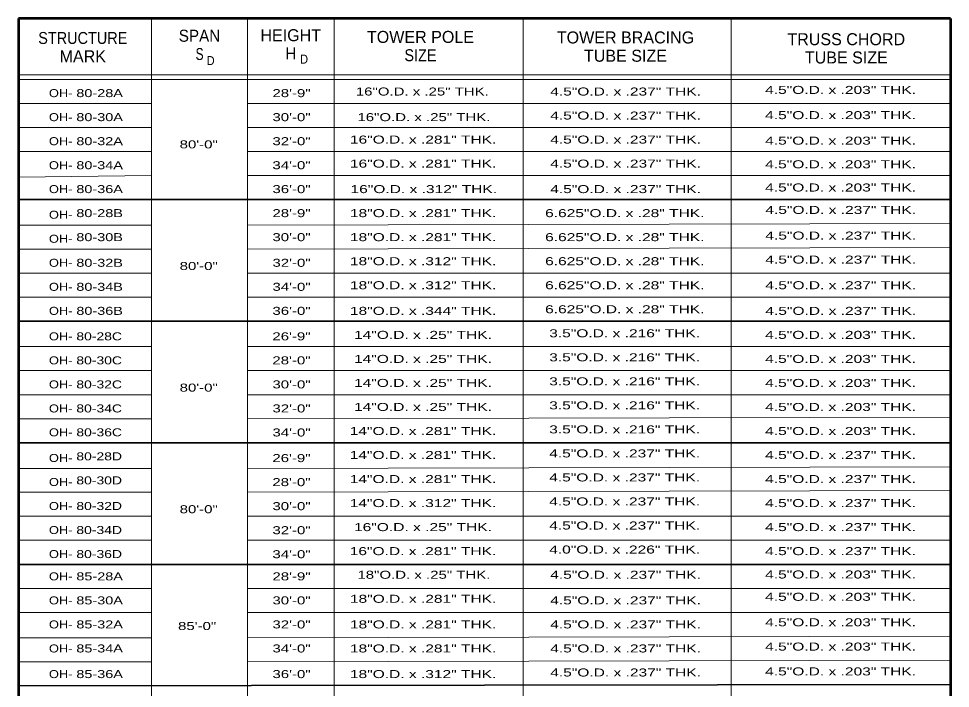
# Model space of a CAD drawing. Extents: x -34832.9 to -34825.9, y -181503 to -181493.
# Drawn here: x -34832.9 to -34825.93, y -181498.01 to -181492.99 of the extents above; entities that cross this region are included whole.
import ezdxf
from ezdxf.enums import TextEntityAlignment as Align

# ---------------------------------------------------------------- set-up
doc = ezdxf.new("R2010")
doc.units = 0
doc.header["$LTSCALE"] = 0.024
doc.layers.add('1', color=7, linetype='Continuous', lineweight=13)
doc.layers.add('13', color=7, linetype='Continuous')

msp = doc.modelspace()

# ---------------------------------------------------------------- linework, layer by layer
at = {"layer": '1', "lineweight": 53}
for p, q in [((-34825.926, -181492.988), (-34832.903, -181492.988)), ((-34832.903, -181492.988), (-34832.903, -181500.697)), ((-34825.926, -181492.988), (-34825.926, -181500.685))]:
    msp.add_line(p, q, dxfattribs=at)
at = {"layer": '1'}
for p, q in [((-34831.908, -181492.988), (-34831.908, -181500.697)), ((-34831.189, -181492.988), (-34831.189, -181500.697)), ((-34830.541, -181492.988), (-34830.541, -181500.697)), ((-34829.126, -181492.988), (-34829.126, -181500.697)), ((-34827.568, -181492.988), (-34827.568, -181500.697)), ((-34825.926, -181493.408), (-34832.903, -181493.408)), ((-34825.926, -181493.444), (-34832.903, -181493.444)), ((-34831.908, -181493.623), (-34832.903, -181493.623)), ((-34825.926, -181493.623), (-34831.189, -181493.623)), ((-34831.908, -181493.803), (-34832.903, -181493.803)), ((-34825.926, -181493.803), (-34831.189, -181493.803)), ((-34831.908, -181493.983), (-34832.903, -181493.983)), ((-34825.926, -181493.983), (-34831.189, -181493.983)), ((-34831.908, -181494.163), (-34832.903, -181494.175)), ((-34825.926, -181494.163), (-34831.189, -181494.163)), ((-34831.908, -181494.535), (-34832.903, -181494.535)), ((-34825.926, -181494.523), (-34831.189, -181494.535)), ((-34831.908, -181494.714), (-34832.903, -181494.714)), ((-34825.926, -181494.702), (-34831.189, -181494.714)), ((-34831.908, -181494.894), (-34832.903, -181494.894)), ((-34825.926, -181494.894), (-34831.189, -181494.894)), ((-34831.908, -181495.074), (-34832.903, -181495.074)), ((-34825.926, -181495.074), (-34831.189, -181495.074)), ((-34831.908, -181495.445), (-34832.903, -181495.445)), ((-34825.926, -181495.445), (-34831.189, -181495.445)), ((-34831.908, -181495.625), (-34832.903, -181495.625)), ((-34825.926, -181495.625), (-34831.189, -181495.625)), ((-34831.908, -181495.805), (-34832.903, -181495.805)), ((-34825.926, -181495.805), (-34831.189, -181495.805)), ((-34825.926, -181495.973), (-34831.189, -181495.985)), ((-34831.908, -181495.985), (-34832.903, -181495.985)), ((-34831.908, -181496.357), (-34832.903, -181496.357)), ((-34825.926, -181496.345), (-34831.189, -181496.357)), ((-34831.908, -181496.536), (-34832.903, -181496.536)), ((-34825.926, -181496.524), (-34831.189, -181496.536)), ((-34831.908, -181496.716), (-34832.903, -181496.716)), ((-34825.926, -181496.716), (-34831.189, -181496.716)), ((-34831.908, -181496.896), (-34832.903, -181496.896)), ((-34825.926, -181496.896), (-34831.189, -181496.896)), ((-34831.908, -181497.256), (-34832.903, -181497.256)), ((-34825.926, -181497.256), (-34831.189, -181497.256)), ((-34831.908, -181497.436), (-34832.903, -181497.436)), ((-34825.926, -181497.436), (-34831.189, -181497.436)), ((-34831.908, -181497.627), (-34832.903, -181497.627)), ((-34825.926, -181497.615), (-34831.189, -181497.627)), ((-34831.908, -181497.807), (-34832.903, -181497.807)), ((-34825.926, -181497.795), (-34831.189, -181497.807))]:
    msp.add_line(p, q, dxfattribs=at)
at = {"layer": '1', "lineweight": 35}
for p, q in [((-34825.926, -181494.343), (-34832.903, -181494.343)), ((-34825.926, -181495.254), (-34832.903, -181495.254)), ((-34825.926, -181496.165), (-34832.903, -181496.165)), ((-34825.926, -181497.076), (-34832.903, -181497.076)), ((-34825.926, -181497.975), (-34832.903, -181497.987))]:
    msp.add_line(p, q, dxfattribs=at)

# ---------------------------------------------------------------- texts
at = {"layer": '13'}
for s, height, width, p in [('STRUCTURE', 0.08991, 0.9, (-34832.4225, -181493.178)), ('SPAN', 0.08991, 0.95, (-34831.5485, -181493.161)), ('S', 0.0899, 0.75, (-34831.548, -181493.298)), ('H', 0.0899, 0.95, (-34830.8645, -181493.294)), ('D', 0.0674, 0.9, (-34830.765, -181493.325)), ('SIZE', 0.08991, 0.9, (-34829.894, -181493.307)), ('D', 0.0674, 0.9, (-34831.465, -181493.336)), ('OH-', 0.05992, 1.2, (-34832.588, -181493.576)), ('28\'-9"', 0.05992, 1.4, (-34830.8595, -181493.576)), ('16"O.D. x .25" THK.', 0.05992, 1.4, (-34829.88, -181493.564)), ('4.5"O.D. x .237" THK.', 0.05992, 1.45, (-34828.358, -181493.564)), ('4.5"O.D. x .203" THK.', 0.06, 1.45, (-34826.748, -181493.552)), ('OH-', 0.05992, 1.2, (-34832.588, -181493.756)), ('30\'-0"', 0.05992, 1.4, (-34830.8595, -181493.756)), ('16"O.D. x .25" THK.', 0.05992, 1.4, (-34829.868, -181493.756)), ('4.5"O.D. x .237" THK.', 0.05992, 1.45, (-34828.358, -181493.744)), ('4.5"O.D. x .203" THK.', 0.06, 1.45, (-34826.748, -181493.741)), ('OH-', 0.05992, 1.2, (-34832.588, -181493.936)), ('32\'-0"', 0.05992, 1.4, (-34830.8595, -181493.936)), ('16"O.D. x .281" THK.', 0.05992, 1.45, (-34829.874, -181493.924)), ('4.5"O.D. x .237" THK.', 0.05992, 1.45, (-34828.358, -181493.924)), ('4.5"O.D. x .203" THK.', 0.06, 1.45, (-34826.748, -181493.932)), ('80\'-0"', 0.05992, 1.4, (-34831.5545, -181493.96)), ('OH-', 0.05992, 1.2, (-34832.588, -181494.116)), ('34\'-0"', 0.05992, 1.4, (-34830.8595, -181494.116)), ('16"O.D. x .281" THK.', 0.05992, 1.45, (-34829.874, -181494.104)), ('4.5"O.D. x .237" THK.', 0.05992, 1.45, (-34828.358, -181494.104)), ('4.5"O.D. x .203" THK.', 0.06, 1.45, (-34826.748, -181494.109)), ('OH-', 0.05992, 1.2, (-34832.588, -181494.295)), ('36\'-0"', 0.05992, 1.4, (-34830.8595, -181494.295)), ('16"O.D. x .312" THK.', 0.06, 1.45, (-34829.869, -181494.295)), ('4.5"O.D. x .237" THK.', 0.05992, 1.45, (-34828.358, -181494.295)), ('4.5"O.D. x .203" THK.', 0.06, 1.45, (-34826.748, -181494.283)), ('OH-', 0.05992, 1.2, (-34832.588, -181494.487)), ('28\'-9"', 0.05992, 1.4, (-34830.8595, -181494.475)), ('18"O.D. x .281" THK.', 0.05992, 1.45, (-34829.874, -181494.475)), ('6.625"O.D. x .28" THK.', 0.05992, 1.45, (-34828.364, -181494.475)), ('4.5"O.D. x .237" THK.', 0.05992, 1.45, (-34826.747, -181494.451)), ('4.5"O.D. x .237" THK.', 0.05992, 1.45, (-34826.747, -181494.643)), ('OH-', 0.05992, 1.2, (-34832.588, -181494.667)), ('30\'-0"', 0.05992, 1.4, (-34830.8595, -181494.655)), ('18"O.D. x .281" THK.', 0.05992, 1.45, (-34829.874, -181494.655)), ('6.625"O.D. x .28" THK.', 0.05992, 1.45, (-34828.364, -181494.655)), ('OH-', 0.05992, 1.2, (-34832.588, -181494.847)), ('32\'-0"', 0.05992, 1.4, (-34830.8595, -181494.847)), ('18"O.D. x .312" THK.', 0.05992, 1.45, (-34829.874, -181494.835)), ('6.625"O.D. x .28" THK.', 0.05992, 1.45, (-34828.364, -181494.835)), ('4.5"O.D. x .237" THK.', 0.05992, 1.45, (-34826.747, -181494.823)), ('80\'-0"', 0.05992, 1.4, (-34831.5545, -181494.871)), ('OH-', 0.05992, 1.2, (-34832.588, -181495.027)), ('34\'-0"', 0.05992, 1.4, (-34830.8595, -181495.027)), ('18"O.D. x .312" THK.', 0.05992, 1.45, (-34829.874, -181495.015)), ('6.625"O.D. x .28" THK.', 0.05992, 1.45, (-34828.364, -181495.015)), ('4.5"O.D. x .237" THK.', 0.05992, 1.45, (-34826.747, -181495.015)), ('6.625"O.D. x .28" THK.', 0.05992, 1.45, (-34828.364, -181495.195)), ('OH-', 0.05992, 1.2, (-34832.588, -181495.207)), ('36\'-0"', 0.05992, 1.4, (-34830.8595, -181495.207)), ('18"O.D. x .344" THK.', 0.05992, 1.45, (-34829.874, -181495.207)), ('4.5"O.D. x .237" THK.', 0.05992, 1.45, (-34826.747, -181495.207)), ('OH-', 0.05992, 1.2, (-34832.588, -181495.398)), ('26\'-9"', 0.06, 1.4, (-34830.86, -181495.398)), ('14"O.D. x .25" THK.', 0.06, 1.45, (-34829.875, -181495.387)), ('3.5"O.D. x .216" THK.', 0.06, 1.45, (-34828.365, -181495.375)), ('4.5"O.D. x .203" THK.', 0.06, 1.45, (-34826.748, -181495.387)), ('OH-', 0.05992, 1.2, (-34832.588, -181495.578)), ('28\'-0"', 0.06, 1.4, (-34830.86, -181495.578)), ('14"O.D. x .25" THK.', 0.06, 1.45, (-34829.875, -181495.567)), ('3.5"O.D. x .216" THK.', 0.06, 1.45, (-34828.365, -181495.555)), ('4.5"O.D. x .203" THK.', 0.06, 1.45, (-34826.748, -181495.567)), ('OH-', 0.05992, 1.2, (-34832.588, -181495.758)), ('30\'-0"', 0.05992, 1.4, (-34830.8595, -181495.758)), ('14"O.D. x .25" THK.', 0.06, 1.45, (-34829.875, -181495.747)), ('3.5"O.D. x .216" THK.', 0.06, 1.45, (-34828.365, -181495.735)), ('4.5"O.D. x .203" THK.', 0.06, 1.45, (-34826.748, -181495.747)), ('80\'-0"', 0.05992, 1.4, (-34831.5545, -181495.782)), ('OH-', 0.05992, 1.2, (-34832.588, -181495.938)), ('32\'-0"', 0.05992, 1.4, (-34830.8595, -181495.938)), ('14"O.D. x .25" THK.', 0.06, 1.45, (-34829.875, -181495.927)), ('3.5"O.D. x .216" THK.', 0.06, 1.45, (-34828.365, -181495.915)), ('4.5"O.D. x .203" THK.', 0.06, 1.45, (-34826.748, -181495.927)), ('14"O.D. x .281" THK.', 0.06, 1.45, (-34829.875, -181496.107)), ('3.5"O.D. x .216" THK.', 0.06, 1.45, (-34828.365, -181496.095)), ('4.5"O.D. x .203" THK.', 0.06, 1.45, (-34826.748, -181496.107)), ('OH-', 0.05992, 1.2, (-34832.588, -181496.117)), ('34\'-0"', 0.05992, 1.4, (-34830.8595, -181496.118)), ('OH-', 0.05992, 1.2, (-34832.588, -181496.309)), ('26\'-9"', 0.06, 1.4, (-34830.86, -181496.31)), ('14"O.D. x .281" THK.', 0.06, 1.45, (-34829.875, -181496.287)), ('4.5"O.D. x .237" THK.', 0.06, 1.45, (-34828.365, -181496.275)), ('4.5"O.D. x .237" THK.', 0.06, 1.45, (-34826.748, -181496.287)), ('4.5"O.D. x .237" THK.', 0.06, 1.45, (-34828.365, -181496.455)), ('OH-', 0.05992, 1.2, (-34832.588, -181496.489)), ('28\'-0"', 0.06, 1.4, (-34830.86, -181496.49)), ('14"O.D. x .281" THK.', 0.06, 1.45, (-34829.875, -181496.467)), ('4.5"O.D. x .237" THK.', 0.06, 1.45, (-34826.748, -181496.467)), ('14"O.D. x .312" THK.', 0.06, 1.45, (-34829.875, -181496.647)), ('4.5"O.D. x .237" THK.', 0.06, 1.45, (-34828.365, -181496.635)), ('4.5"O.D. x .237" THK.', 0.06, 1.45, (-34826.748, -181496.647)), ('OH-', 0.05992, 1.2, (-34832.588, -181496.669)), ('80\'-0"', 0.05992, 1.4, (-34831.5545, -181496.693)), ('30\'-0"', 0.05992, 1.4, (-34830.8595, -181496.67)), ('OH-', 0.05992, 1.2, (-34832.588, -181496.849)), ('32\'-0"', 0.05992, 1.4, (-34830.8595, -181496.85)), ('16"O.D. x .25" THK.', 0.06, 1.45, (-34829.875, -181496.827)), ('4.5"O.D. x .237" THK.', 0.06, 1.45, (-34828.365, -181496.815)), ('4.5"O.D. x .237" THK.', 0.06, 1.45, (-34826.748, -181496.827)), ('16"O.D. x .281" THK.', 0.06, 1.45, (-34829.875, -181497.007)), ('4.0"O.D. x .226" THK.', 0.06, 1.45, (-34828.365, -181496.995)), ('4.5"O.D. x .237" THK.', 0.06, 1.45, (-34826.748, -181497.007)), ('OH-', 0.05992, 1.2, (-34832.588, -181497.029)), ('34\'-0"', 0.05992, 1.4, (-34830.8595, -181497.03)), ('OH-', 0.05992, 1.2, (-34832.588, -181497.196)), ('28\'-9"', 0.05992, 1.4, (-34830.8595, -181497.196)), ('18"O.D. x .25" THK.', 0.05992, 1.4, (-34829.868, -181497.184)), ('4.5"O.D. x .237" THK.', 0.05992, 1.45, (-34828.358, -181497.184)), ('4.5"O.D. x .203" THK.', 0.06, 1.45, (-34826.748, -181497.182)), ('18"O.D. x .281" THK.', 0.05992, 1.45, (-34829.874, -181497.364)), ('4.5"O.D. x .203" THK.', 0.06, 1.45, (-34826.748, -181497.349)), ('OH-', 0.05992, 1.2, (-34832.588, -181497.376)), ('30\'-0"', 0.05992, 1.4, (-34830.8595, -181497.376)), ('4.5"O.D. x .237" THK.', 0.05992, 1.45, (-34828.358, -181497.376)), ('OH-', 0.05992, 1.2, (-34832.588, -181497.556)), ('85\'-0"', 0.05992, 1.4, (-34831.5665, -181497.568)), ('32\'-0"', 0.05992, 1.4, (-34830.8595, -181497.556)), ('18"O.D. x .281" THK.', 0.05992, 1.45, (-34829.874, -181497.556)), ('4.5"O.D. x .237" THK.', 0.05992, 1.45, (-34828.358, -181497.556)), ('4.5"O.D. x .203" THK.', 0.06, 1.45, (-34826.748, -181497.54)), ('OH-', 0.05992, 1.2, (-34832.588, -181497.736)), ('34\'-0"', 0.05992, 1.4, (-34830.8595, -181497.736)), ('18"O.D. x .281" THK.', 0.05992, 1.45, (-34829.874, -181497.736)), ('4.5"O.D. x .237" THK.', 0.05992, 1.45, (-34828.358, -181497.736)), ('4.5"O.D. x .203" THK.', 0.06, 1.45, (-34826.748, -181497.722)), ('4.5"O.D. x .237" THK.', 0.05992, 1.45, (-34828.358, -181497.916)), ('4.5"O.D. x .203" THK.', 0.06, 1.45, (-34826.748, -181497.908)), ('OH-', 0.05992, 1.2, (-34832.588, -181497.928)), ('36\'-0"', 0.05992, 1.4, (-34830.8595, -181497.928)), ('18"O.D. x .312" THK.', 0.05992, 1.45, (-34829.874, -181497.928))]:
    msp.add_text(s, height=height, dxfattribs=dict(at, width=width)).set_placement(p, align=Align.CENTER)
for s, p in [('HEIGHT', (-34830.8655, -181493.157)), ('TOWER POLE', (-34829.894, -181493.17)), ('TOWER BRACING', (-34828.3585, -181493.174)), ('TRUSS CHORD', (-34826.7055, -181493.187)), ('MARK', (-34832.4225, -181493.315)), ('TUBE SIZE', (-34828.359, -181493.311)), ('TUBE SIZE', (-34826.705, -181493.324))]:
    msp.add_text(s, height=0.08991, dxfattribs=at).set_placement(p, align=Align.CENTER)
for s, height, width, p in [('80-28A', 0.05992, 1.35, (-34832.471, -181493.576)), ('80-30A', 0.05992, 1.35, (-34832.471, -181493.756)), ('80-32A', 0.05992, 1.35, (-34832.471, -181493.936)), ('80-34A', 0.05992, 1.35, (-34832.471, -181494.116)), ('80-36A', 0.05992, 1.35, (-34832.471, -181494.295)), ('80-28B', 0.05992, 1.35, (-34832.471, -181494.475)), ('80-30B', 0.05992, 1.35, (-34832.471, -181494.655)), ('80-32B', 0.05992, 1.35, (-34832.471, -181494.847)), ('80-34B', 0.05992, 1.35, (-34832.471, -181495.027)), ('80-36B', 0.05992, 1.35, (-34832.471, -181495.207)), ('80-28C', 0.06, 1.3, (-34832.471, -181495.398)), ('80-30C', 0.06, 1.3, (-34832.471, -181495.578)), ('80-32C', 0.06, 1.3, (-34832.471, -181495.758)), ('80-34C', 0.06, 1.3, (-34832.471, -181495.938)), ('80-36C', 0.06, 1.3, (-34832.471, -181496.117)), ('80-28D', 0.06, 1.3, (-34832.471, -181496.297)), ('80-30D', 0.06, 1.3, (-34832.471, -181496.477)), ('80-32D', 0.06, 1.3, (-34832.471, -181496.669)), ('80-34D', 0.06, 1.3, (-34832.471, -181496.849)), ('80-36D', 0.06, 1.3, (-34832.471, -181497.029)), ('85-28A', 0.05992, 1.35, (-34832.471, -181497.196)), ('85-30A', 0.05992, 1.35, (-34832.471, -181497.376)), ('85-32A', 0.05992, 1.35, (-34832.471, -181497.556)), ('85-34A', 0.05992, 1.35, (-34832.471, -181497.736)), ('85-36A', 0.05992, 1.35, (-34832.471, -181497.928))]:
    msp.add_text(s, height=height, dxfattribs=dict(at, width=width)).set_placement(p)

doc.saveas('drawing.dxf')
